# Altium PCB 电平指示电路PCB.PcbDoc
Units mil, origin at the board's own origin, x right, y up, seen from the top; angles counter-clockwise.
Board outline 3900 x 1800 mil, 2 copper layers (Top Layer, Bottom Layer); 18 components, 13 nets, 36 pads, 0 vias.
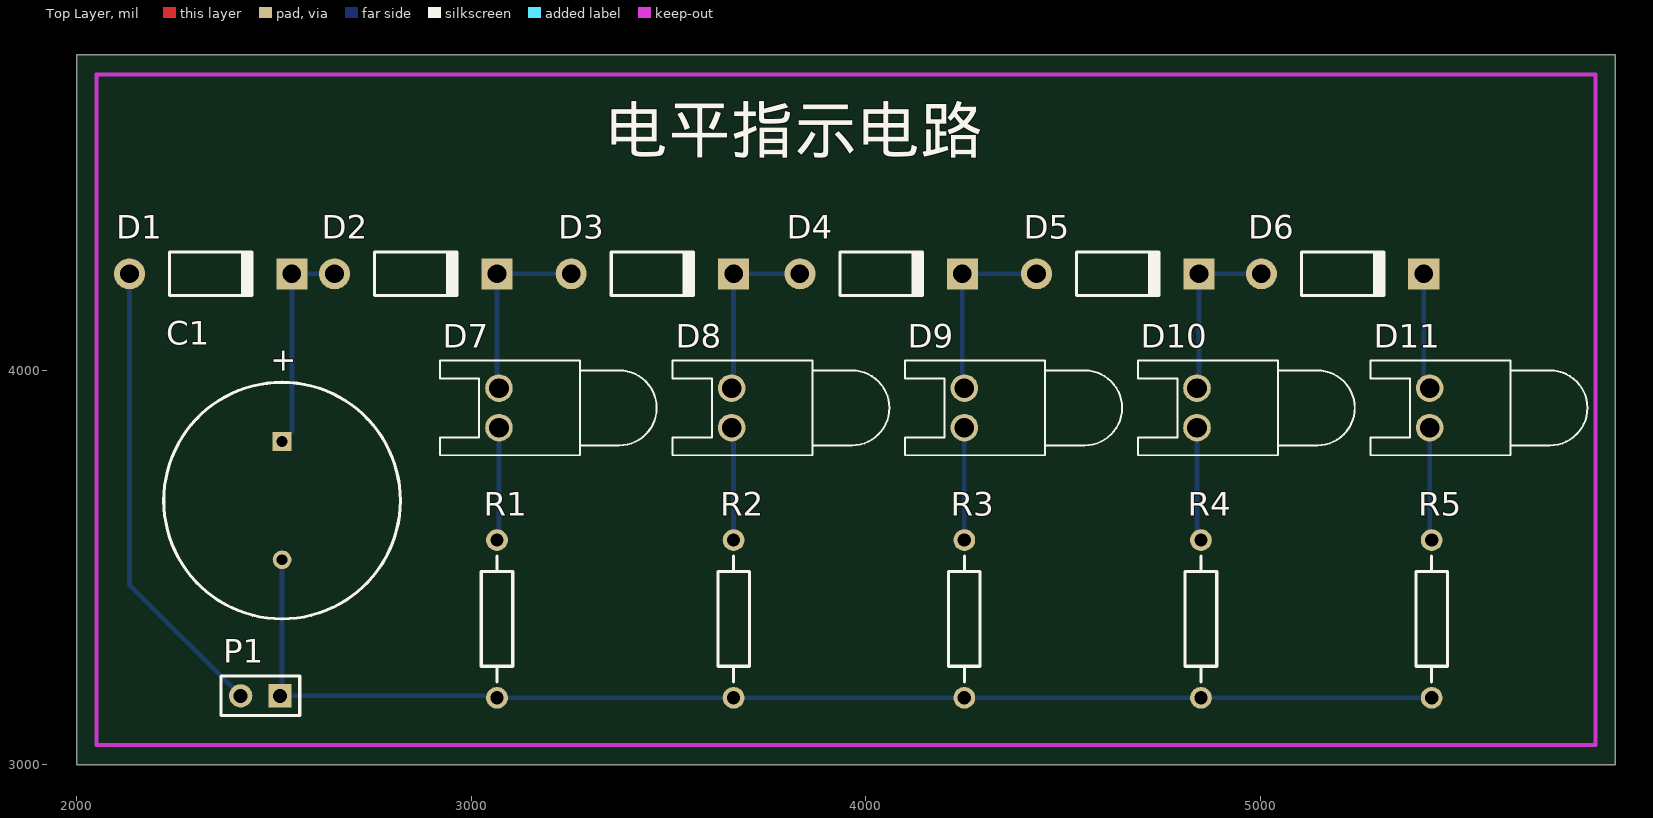
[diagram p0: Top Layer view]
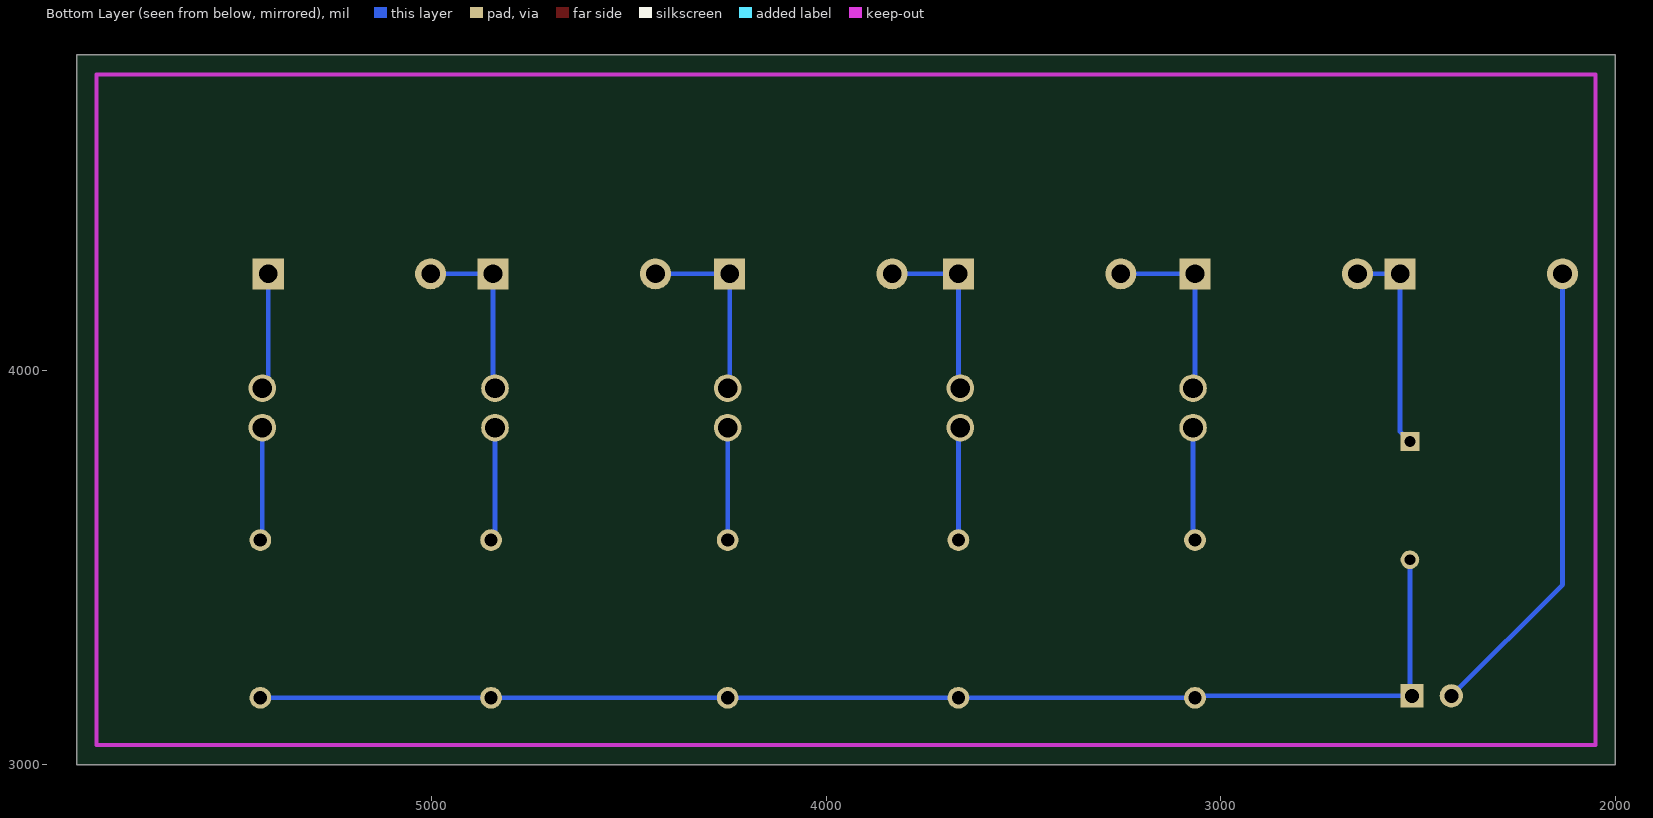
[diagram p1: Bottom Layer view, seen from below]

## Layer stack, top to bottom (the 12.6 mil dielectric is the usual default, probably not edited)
Top Solder: solder mask 0.4, Solder Resist, Dk 3.5
Top Layer: signal copper 1.4
Dielectric 1: dielectric 12.6, FR-4, Dk 4.8
Bottom Layer: signal copper 1.4
Bottom Solder: solder mask 0.4, Solder Resist, Dk 3.5

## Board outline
2000,3000 5900,3000 5900,4800 2000,4800

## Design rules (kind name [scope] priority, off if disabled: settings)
Clearance [All] p1: gap=13
PolygonConnect [All] p1: connectstyle=Relief reliefconductorwidth=10 reliefentries=4 polygonreliefangle="90 Angle" airgapwidth=10
RoutingVias [All] p1: holewidth=32 width=62 viastyle="Through Hole" minholewidth=28 minwidth=50 maxholewidth=28 maxwidth=50
SolderMaskExpansion [All] p1: expansion=4
Width [All] p1: maxlimit=12 minlimit=12 preferedwidth=12
30 further rules are at their usual default settings.

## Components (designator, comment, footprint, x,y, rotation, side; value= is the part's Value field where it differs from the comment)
C1 "Cap Pol1" RB7.6-15 2520,3670 r90 top
D1 "Diode 1N4007" DO-41 2339.09,4245 r0 top
D2 "Diode 1N4007" DO-41 2859.09,4245 r0 top
D3 "Diode 1N4007" DO-41 3459.09,4245 r0 top
D4 "Diode 1N4007" DO-41 4039.09,4245 r0 top
D5 "Diode 1N4007" DO-41 4639.09,4245 r0 top
D6 "Diode 1N4007" DO-41 5209.09,4245 r0 top
D7 "LED0" LED-0 3070,3905 r90 top
D8 "LED0" LED-0 3660,3905 r90 top
D9 "LED0" LED-0 4250,3905 r90 top
D10 "LED0" LED-0 4840,3905 r90 top
D11 "LED0" LED-0 5430,3905 r90 top
P1 "Header 2" HDR1X2 2515,3175 r180 top
R1 "Res2" AXIAL-0.4 3065,3370 r90 top
R2 "Res2" AXIAL-0.4 3665,3370 r270 top
R3 "Res2" AXIAL-0.4 4250,3370 r270 top
R4 "Res2" AXIAL-0.4 4850,3370 r270 top
R5 "Res2" AXIAL-0.4 5435,3370 r270 top

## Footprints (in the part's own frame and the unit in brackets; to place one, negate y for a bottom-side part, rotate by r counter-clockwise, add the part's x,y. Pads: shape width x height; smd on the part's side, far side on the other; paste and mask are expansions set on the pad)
AXIAL-0.4 [mm] "Axial Device, Thru-Hole; 2 Leads; 0.4 in Pin Spacing"
  round 1.4 hole 0.85: 1(-5.08,0) 2(5.08,0)
  silkscreen extent -4.06,-1.02 4.06,1.02
DO-41 [mm] "Diode, Axial; Body 5.2 x 2.7 mm (LxDia. max), Lead Dia. 0.86 mm (max)"
  round 2 hole 1.2: 1(-5.23,0)
  rect 2x2 hole 1.2: 2(5.23,0)
  silkscreen extent -2.65,-1.4 2.75,1.4
HDR1X2 [mm] "Connector; Header; 2 Position"
  rect 1.5x1.5 hole 0.9: 1(0,0)
  round 1.5 hole 0.9: 2(2.54,0)
  silkscreen extent -1.27,-1.27 3.81,1.27
LED-0 [mil] "LED; 2 Leads"
  round 70 hole 50: 1(50,0) 2(-50,0)
  silkscreen extent -120,-400 120,150
RB7.6-15 [mm] "Polarized Capacitor (Radial); 2 Leads"
  rect 1.2x1.2 hole 0.7: 1(3.81,0)
  round 1.2 hole 0.7: 2(-3.81,0)
  silkscreen extent -7.62,-7.62 7.62,7.62

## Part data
C1: "Polarized Capacitor (Radial)"
D1 D2 D3 D4 D5 D6: "1 Amp General Purpose Rectifier"
D7 D8 D9 D10 D11: "Typical INFRARED GaAs LED"
P1: "Header, 2-Pin"
R1 R2 R3 R4 R5: "Resistor"

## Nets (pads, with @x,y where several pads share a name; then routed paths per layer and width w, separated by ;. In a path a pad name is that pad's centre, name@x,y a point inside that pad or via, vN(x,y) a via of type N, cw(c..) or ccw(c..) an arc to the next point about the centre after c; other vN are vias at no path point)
GND: C1.2 P1.1 R1.1 R2.2 R3.2 R4.2 R5.2 | length 3269.1
  Bottom Layer w12: C1.2 2520,3180 P1.1 3060,3175 R1.1 R2.2 R3.2 R4.2 R5.2
NetC1_1: C1.1 D1.2 D2.1 | length 543.5
  Bottom Layer w12: C1.1 2545,3845 D1.2 D2.1
NetD2_2: D2.2 D3.1 D7.1 | length 480.3
  Bottom Layer w12: D7.1 3065,3960 D2.2 D3.1
NetD3_2: D3.2 D4.1 D8.1 | length 460.3
  Bottom Layer w12: D8.1 3665,3960 D3.2 D4.1
NetD4_2: D4.2 D5.1 D9.1 | length 480.3
  Bottom Layer w12: D9.1 4245,3960 D4.2 D5.1
NetD5_2: D5.2 D6.1 D10.1 | length 450.3
  Bottom Layer w12: D10.1 4845,3960 D5.2 D6.1
NetD6_2: D6.2 D11.1 | length 296.2
  Bottom Layer w12: D6.2 5415,3970 D11.1
NetD7_2: D7.2 R1.2 | length 287.1
  Bottom Layer w12: R1.2 3070,3575 D7.2
NetD8_2: D8.2 R2.1 | length 287.1
  Bottom Layer w12: D8.2 3665,3850 R2.1
NetD9_2: D9.2 R3.1 | length 285
  Bottom Layer w12: R3.1 D9.2
NetD10_2: D10.2 R4.1 | length 289.1
  Bottom Layer w12: D10.2 4840,3580 R4.1
NetD11_2: D11.2 R5.1 | length 287.1
  Bottom Layer w12: D11.2 5430,3575 R5.1
VCC: D1.1 P1.2 | length 1186.7
  Bottom Layer w12: D1.1 2133.19,3456.81 P1.2

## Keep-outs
Keep-Out Layer:
  lines w10: 2050,3050 5850,3050 5850,4750 2050,4750 2050,3050

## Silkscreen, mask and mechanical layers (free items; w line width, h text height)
Top Overlay:
  text "电平指示电路" at 3340,4515 h200
  text "电平指示电路" at 6270,0 h200
Drill Drawing:
  text ".LEGEND" at 6100,3210 h60
  text "Drill Drawing." at 6100,3100 h60

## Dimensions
2050,3050 to 5850,3050 on Mechanical 1
2050,3050 to 2050,4750 on Mechanical 1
